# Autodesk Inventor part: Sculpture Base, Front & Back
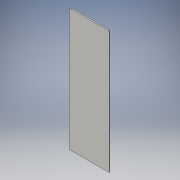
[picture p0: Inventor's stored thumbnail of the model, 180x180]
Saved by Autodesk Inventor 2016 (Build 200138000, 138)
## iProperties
Created: 2015-08
Part Number: Sculpture Base, Front & Back
Material: Wood (Birch)
Document SubType Name: Modeling
Designer: Chris Eckert
Density: 0.55 g/cm^3
Appearance: Birch - Natural Polished
Author: Chris Eckert
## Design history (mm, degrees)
sketch "Sketch1"
  geometry: L1 (-185.738, 596.9)-(185.737, 596.9); L2 (185.737, 596.9)-(185.738, -596.9); L3 (185.738, -596.9)-(-185.737, -596.9); L4 (-185.737, -596.9)-(-185.738, 596.9); 1 further point
  constraints: 8 end point, 2 parallel, 1 horizontal, 1 perpendicular
  dimensions: "d0" = 1193.8 distance of L3.end L1.start (= OverallHeight); "d1" = 371.475 distance of L1.start L1.end (= OverallWidth + 2 x DatoOverhang); "d2" = 185.7375 distance from line of L4 point (0, 0) (= 0.5 x d1); "d3" = 596.9 distance from line of L1 point (0, 0) (= 0.5 x d0)
extrude "Extrusion1" new body sketch "Sketch1" distance "d4" = 12.7 (= WoodThickness); taper "d5" = 0 deg
sketch "Sketch2"
  geometry: L1 (-185.737, 596.9)-(185.738, 596.9) reference; L2 (185.737, -596.9)-(-185.737, -596.9) reference; L3 (-185.737, 596.9)-(-171.45, 596.9); L4 (-171.45, 596.9)-(-171.45, -596.9); L5 (-171.45, -596.9)-(-185.737, -596.9); L6 (-185.737, -596.9)-(-185.737, 596.9); L7 (185.738, 596.9)-(171.45, 596.9); L8 (171.45, 596.9)-(171.45, -596.9); L9 (171.45, -596.9)-(185.738, -596.9); L10 (185.738, -596.9)-(185.738, 596.9); 1 further point
  constraints: 16 end point, 4 parallel, 2 horizontal, 2 perpendicular, 2 point on line
  dimensions: "d6" = 14.2875 distance between parallel lines of L6 L4 (= WoodThickness + DatoOverhang); "d7" = 14.2875 distance between parallel lines of L10 L8 (= d6)
extrude "Extrusion2" cut sketch "Sketch2" distance "d8" = 6.35 (= 0.5 x WoodThickness); taper "d9" = 0 deg
body "Solid1"
other parameters: "WoodThickness" = 12.7 [user parameter; used in 3 equation terms], "OverallHeight" = 1193.8 [user parameter; used in 1 equation term], "OverallWidth" = 368.3 [user parameter; used in 1 equation term], "OverallDepth" = 368.3 [user parameter], "DatoOverhang" = 1.5875 [user parameter; used in 2 equation terms]
